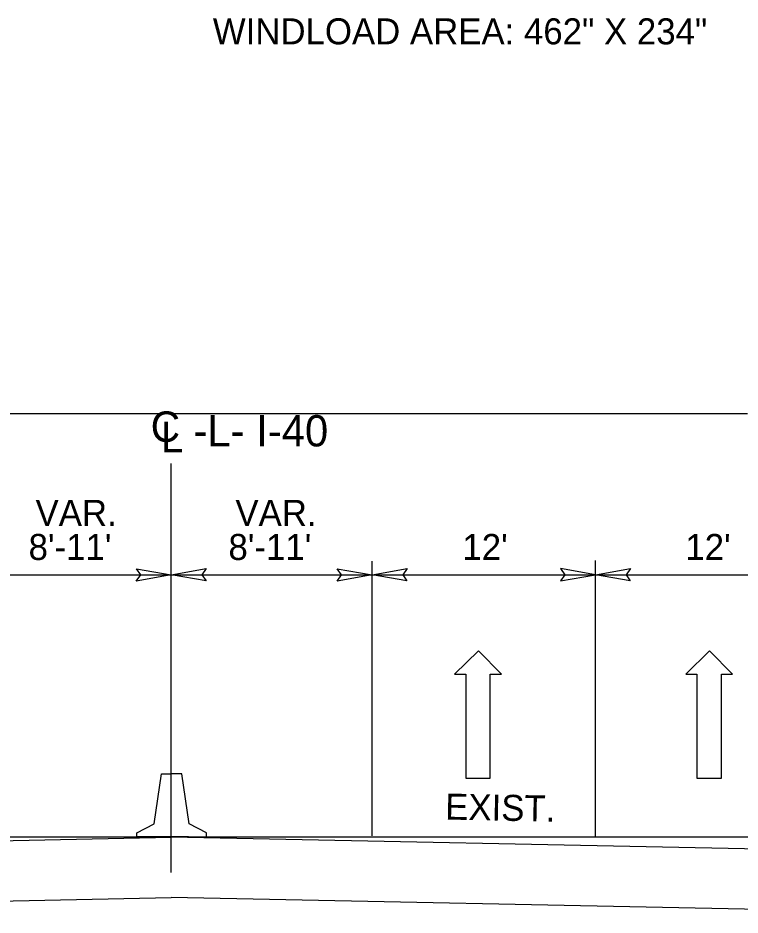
# Model space of a CAD drawing. Extents: x 1725232 to 1728895, y 538685 to 540544.
# Drawn here: x 1725399.83 to 1725438.73, y 539418.42 to 539466.73 of the extents above; entities that cross this region are included whole.
import ezdxf

# ---------------------------------------------------------------- set-up
doc = ezdxf.new("R2010")
doc.units = 0
for name, color, linetype in [('Default', 7, 'Continuous'), ('Typical Pavement Slope CELL', 7, 'Continuous'), ('Typical Pavement Slope Information CELL', 7, 'Continuous'), ('Typical Text Centerline CELL', 7, 'Continuous')]:
    doc.layers.add(name, color=color, linetype=linetype)

msp = doc.modelspace()

# ---------------------------------------------------------------- linework, layer by layer
at = {"layer": 'Default'}
for p, q in [((1725326.199, 539445.427), (1725439.137, 539445.427)), ((1725418.911, 539422.685), (1725418.911, 539437.478)), ((1725430.942, 539422.641), (1725430.942, 539437.509)), ((1725397.292, 539436.739), (1725408.092, 539436.739)), ((1725408.092, 539436.739), (1725418.933, 539436.739)), ((1725418.933, 539436.739), (1725430.942, 539436.739)), ((1725430.942, 539436.739), (1725442.952, 539436.739)), ((1725424.633, 539432.643), (1725423.353, 539431.383)), ((1725425.873, 539431.383), (1725424.633, 539432.643)), ((1725437.085, 539432.643), (1725435.805, 539431.383)), ((1725438.325, 539431.383), (1725437.085, 539432.643)), ((1725423.353, 539431.383), (1725423.953, 539431.383)), ((1725423.953, 539431.383), (1725423.953, 539425.783)), ((1725425.273, 539425.783), (1725425.273, 539431.383)), ((1725425.273, 539431.383), (1725425.873, 539431.383)), ((1725435.805, 539431.383), (1725436.405, 539431.383)), ((1725436.405, 539431.383), (1725436.405, 539425.783)), ((1725437.725, 539425.783), (1725437.725, 539431.383)), ((1725437.725, 539431.383), (1725438.325, 539431.383)), ((1725423.953, 539425.783), (1725425.273, 539425.783)), ((1725436.405, 539425.783), (1725437.725, 539425.783)), ((1725408.092, 539422.604), (1725326.199, 539422.604)), ((1725504.858, 539422.604), (1725408.092, 539422.604))]:
    msp.add_line(p, q, dxfattribs=at)
for points in [[(1725406.216, 539437.062), (1725408.092, 539436.739), (1725406.206, 539436.406), (1725406.445, 539436.739)], [(1725409.967, 539436.416), (1725408.092, 539436.739), (1725409.978, 539437.072), (1725409.738, 539436.739)], [(1725417.036, 539437.062), (1725418.911, 539436.739), (1725417.025, 539436.405), (1725417.265, 539436.739)], [(1725420.787, 539436.416), (1725418.911, 539436.739), (1725420.797, 539437.072), (1725420.558, 539436.739)], [(1725429.067, 539436.416), (1725430.942, 539436.739), (1725429.056, 539437.072), (1725429.296, 539436.739)], [(1725432.818, 539436.416), (1725430.942, 539436.739), (1725432.829, 539437.072), (1725432.589, 539436.739)]]:
    msp.add_lwpolyline(points, close=True, dxfattribs=at)
at = {"layer": 'Typical Pavement Slope CELL'}
for p, q in [((1725407.175, 539423.324), (1725407.569, 539426.027)), ((1725407.569, 539426.027), (1725408.112, 539426.027)), ((1725408.656, 539426.027), (1725408.112, 539426.027)), ((1725409.05, 539423.324), (1725408.656, 539426.027)), ((1725361.242, 539421.667), (1725408.092, 539422.604)), ((1725454.94, 539421.667), (1725408.092, 539422.604)), ((1725361.242, 539418.416), (1725408.092, 539419.353)), ((1725442.281, 539418.672), (1725408.092, 539419.356))]:
    msp.add_line(p, q, dxfattribs=at)
for points in [[(1725409.022, 539422.62), (1725406.231, 539422.62), (1725406.231, 539422.836), (1725407.175, 539423.324)], [(1725407.203, 539422.62), (1725409.994, 539422.62), (1725409.994, 539422.836), (1725409.05, 539423.324)]]:
    msp.add_lwpolyline(points, dxfattribs=at)
at = {"layer": 'Typical Text Centerline CELL'}
msp.add_line((1725408.092, 539420.713), (1725408.092, 539442.731), dxfattribs=at)

# ---------------------------------------------------------------- texts
at = {"layer": 'Typical Pavement Slope Information CELL'}
for s, p in [('WINDLOAD AREA: 462" X 234"', (1725410.331, 539465.311)), ('VAR.', (1725400.782, 539439.377)), ('VAR.', (1725411.548, 539439.376)), ("8'-11'", (1725400.407, 539437.54)), ("8'-11'", (1725411.173, 539437.539)), ("12'", (1725423.775, 539437.539)), ("12'", (1725435.785, 539437.539))]:
    msp.add_text(s, height=1.4011, dxfattribs=at).set_placement(p)
msp.add_text('EXIST.', height=1.4011, rotation=358.8543, dxfattribs=at).set_placement((1725422.836, 539423.561))
at = {"layer": 'Typical Text Centerline CELL'}
for s, height, rotation, p in [('C', 1.64, 0.0443, (1725406.986, 539443.901)), ('-L- I-40', 1.6843, 359.9417, (1725409.287, 539443.663)), ('L', 1.641, 359.9912, (1725407.532, 539443.342))]:
    msp.add_text(s, height=height, rotation=rotation, dxfattribs=at).set_placement(p)

doc.saveas('drawing.dxf')
